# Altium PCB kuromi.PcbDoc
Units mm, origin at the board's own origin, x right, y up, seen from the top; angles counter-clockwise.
Board outline 67.61 x 64.44 mm, 2 copper layers (Top Layer, Bottom Layer); 19 components, 18 nets, 62 pads, 0 vias.
Unrouted connection lines stored in the file: 5.
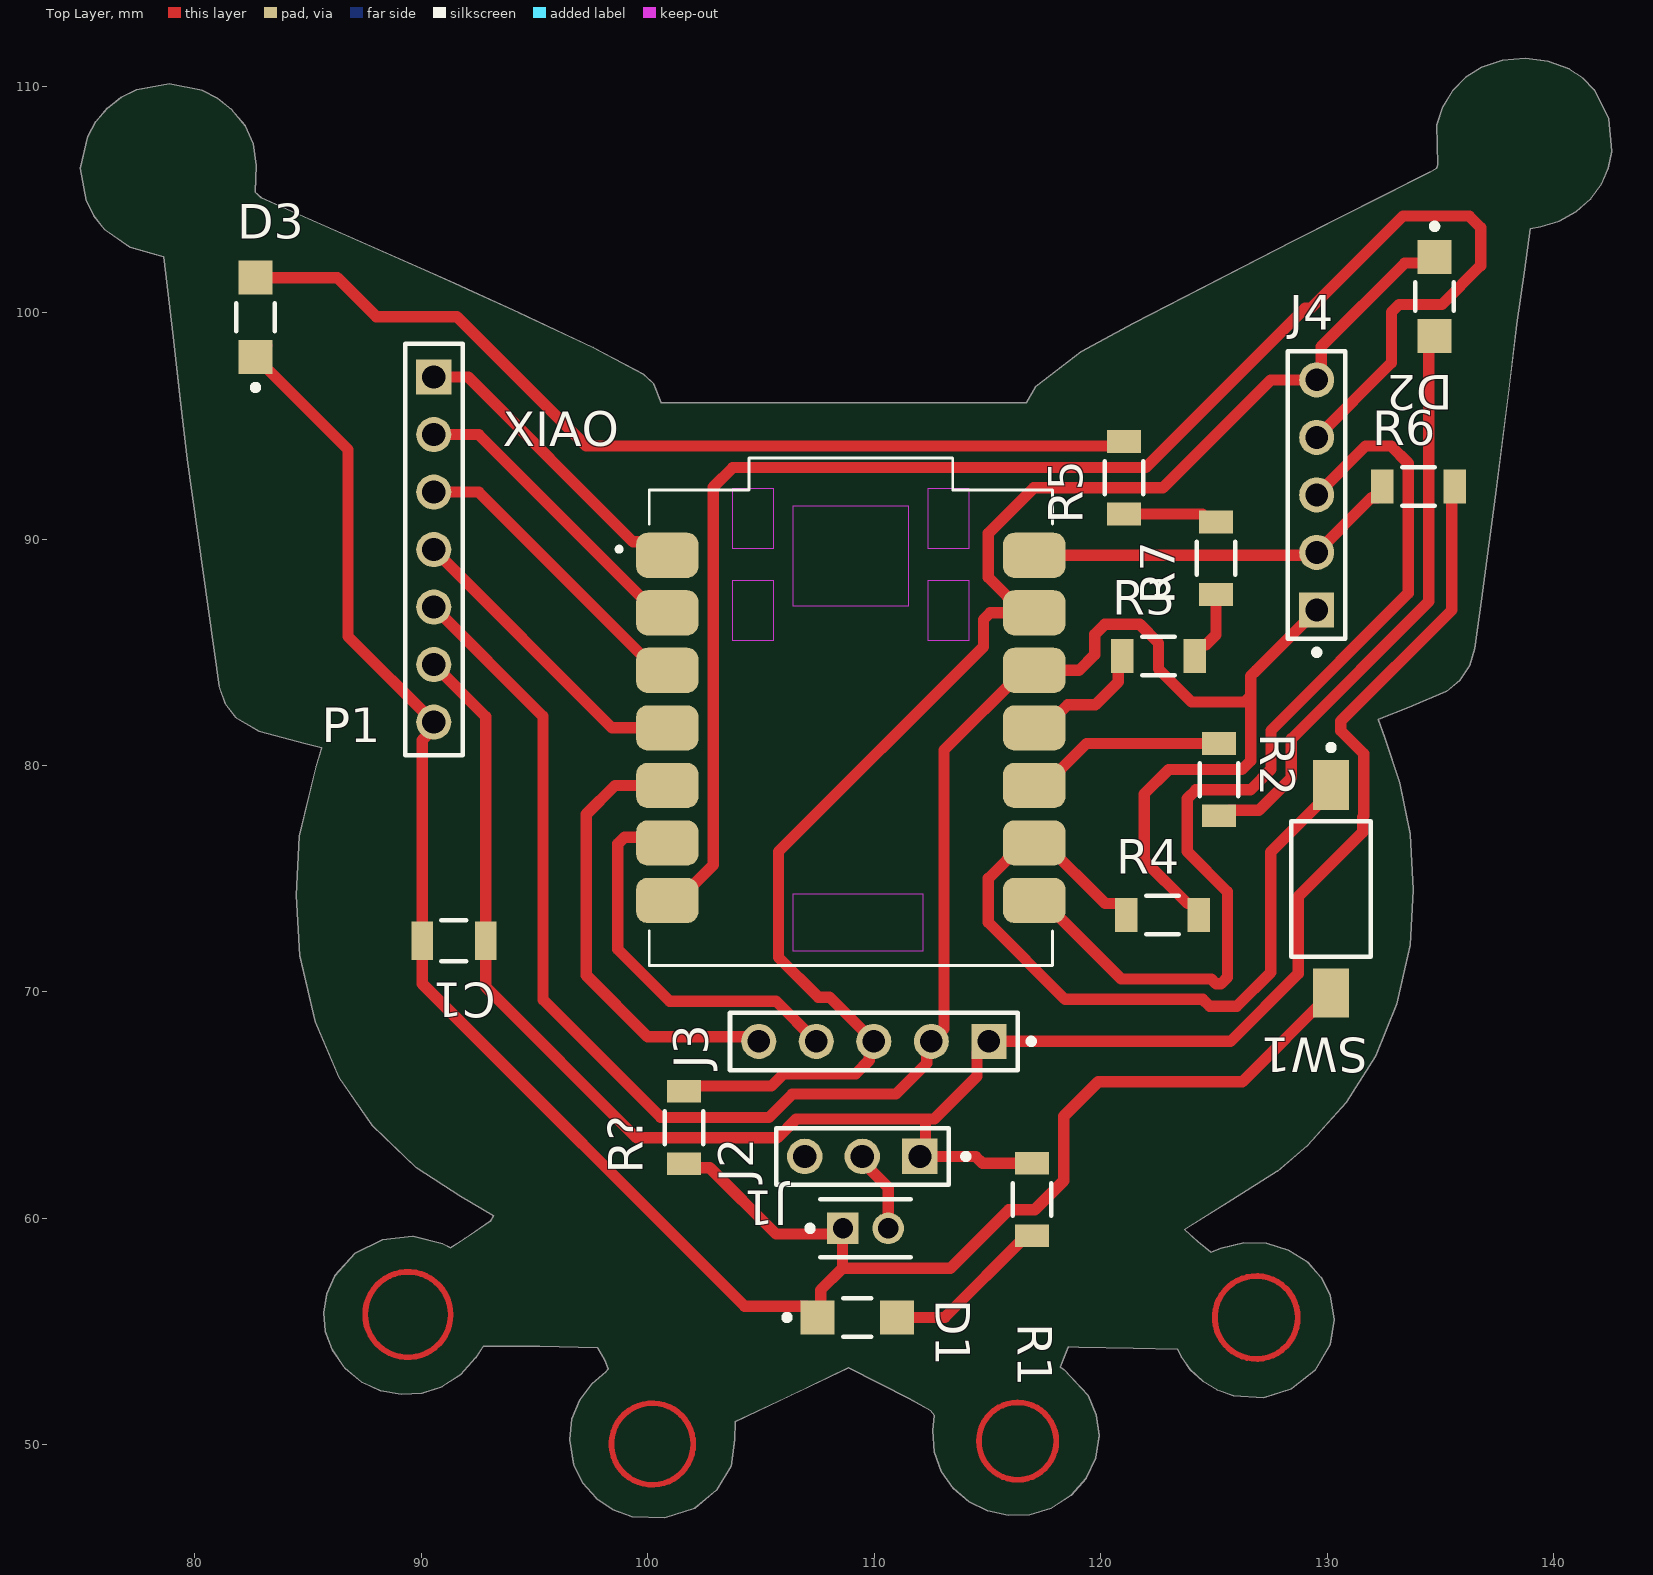
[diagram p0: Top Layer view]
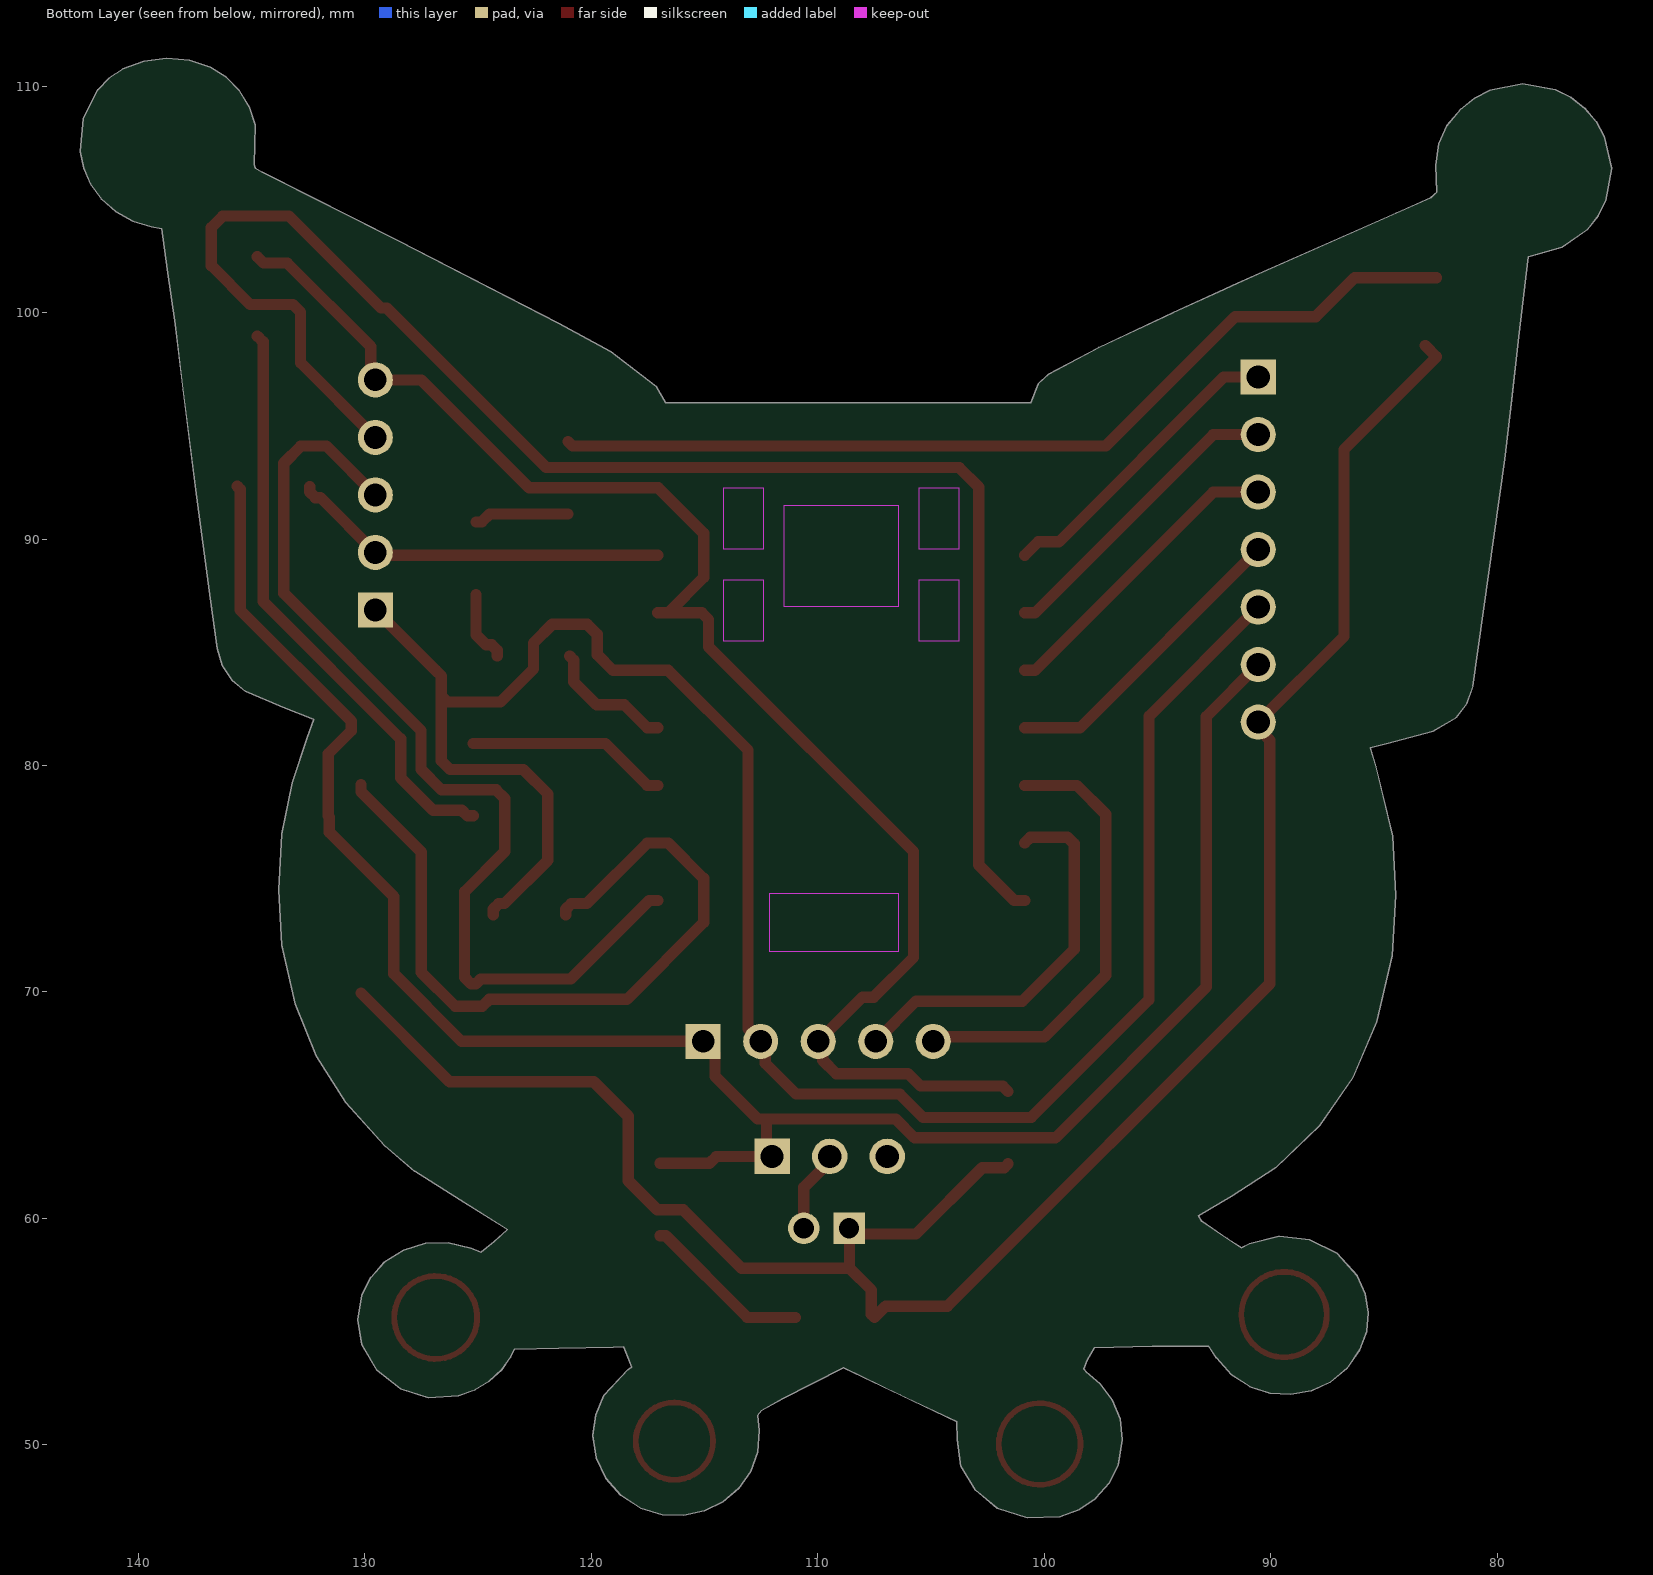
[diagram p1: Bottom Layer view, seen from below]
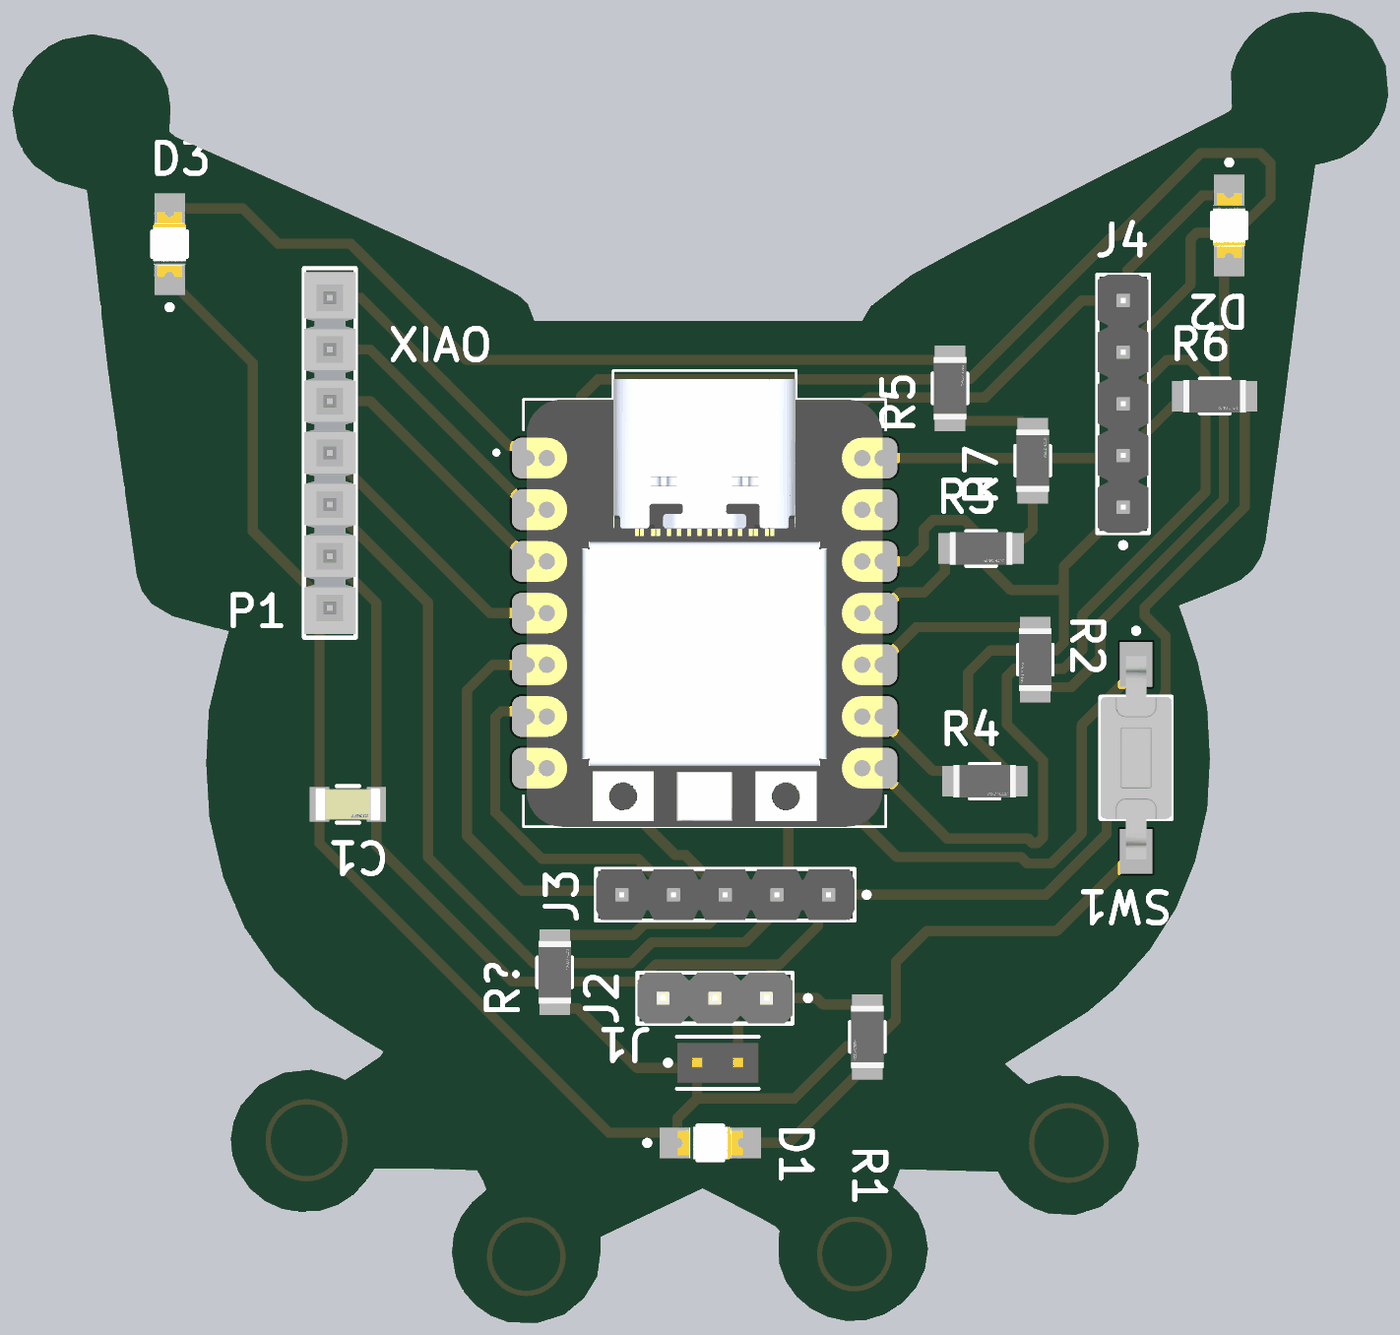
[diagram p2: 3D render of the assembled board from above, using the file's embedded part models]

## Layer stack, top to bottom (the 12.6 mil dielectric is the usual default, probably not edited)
Top Solder: solder mask 0.0102, Solder Resist, Dk 3.5
Top Layer: signal copper 0.0356
Dielectric 1: dielectric 0.32, FR-4, Dk 4.8
Bottom Layer: signal copper 0.0356
Bottom Solder: solder mask 0.0102, Solder Resist, Dk 3.5

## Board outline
86.633,53.379 87.363,52.775 88.206,52.389 89.114,52.226 90.036,52.287 90.923,52.575 91.727,53.093 92.397,53.844 92.749,54.364 95.221,54.364 97.798,54.283 98.098,53.75 98.248,53.349 98.159,53.228 97.542,52.701 96.998,51.982 96.65,51.147 96.557,50.23 96.731,49.113 97.133,48.318 97.723,47.649 98.462,47.14 99.315,46.823 99.316,46.818 100.748,46.779 102.073,47.198 103.043,48.004 103.684,49.063 103.849,50.236 103.862,51.017 106.358,52.204 108.872,53.4 111.55,52.033 112.486,51.515 112.66,51.299 112.583,50.641 112.647,49.682 112.965,48.819 113.493,48.08 114.189,47.492 115.012,47.084 115.92,46.883 116.869,46.916 117.819,47.21 118.697,47.773 119.365,48.529 119.791,49.426 119.942,50.416 119.797,51.317 119.451,52.177 118.382,53.322 118.223,53.428 118.391,53.878 118.56,54.329 119.029,54.321 121.448,54.262 123.397,54.214 123.568,53.88 123.959,53.318 124.505,52.82 125.156,52.422 125.862,52.161 127.193,52.087 128.437,52.487 129.463,53.291 130.14,54.43 130.306,55.524 130.145,56.612 129.734,57.394 129.15,58.067 128.298,58.589 127.318,58.909 126.328,58.924 125.313,58.674 124.867,58.502 124.286,58.979 123.704,59.51 125.79,60.824 127.797,62.075 129.139,63.218 130.845,65.12 132.141,67.174 133.067,69.463 133.667,72.071 133.797,74.51 133.665,76.974 133.202,79.239 132.545,81.24 132.263,82.036 133.621,82.564 135.275,83.27 135.864,83.761 136.299,84.414 136.521,85.168 136.834,87.385 137.479,92.18 138.032,96.623 138.379,99.486 138.718,101.915 138.971,103.696 139.434,103.787 140.249,104.034 140.998,104.454 141.635,105.013 142.116,105.681 142.413,106.385 142.56,107.117 142.434,108.567 141.792,109.843 141.293,110.358 140.685,110.76 139.753,111.097 138.743,111.223 137.738,111.137 136.823,110.837 136.115,110.388 135.538,109.797 135.109,109.089 134.849,108.288 134.885,106.529 134.843,106.383 134.53,106.19 128.526,103.173 121.448,99.529 119.138,98.276 117.134,96.735 116.71,96.012 100.601,96.012 100.274,96.851 99.804,97.283 97.588,98.462 94.323,100.003 92.291,100.927 91.463,101.296 90.529,101.715 84.451,104.4 82.932,105.077 82.656,105.327 82.719,106.509 82.582,107.459 82.223,108.253 81.62,108.972 81.001,109.465 80.323,109.819 78.871,110.112 77.422,109.849 76.749,109.508 76.136,109.028 75.63,108.438 75.263,107.785 74.949,106.369 75.198,104.942 75.534,104.277 76.013,103.671 77.131,102.889 78.305,102.549 78.618,102.465 79.052,98.927 79.354,96.162 79.662,93.529 81.067,83.504 81.335,82.731 81.802,82.121 82.825,81.518 84.896,80.952 85.601,80.786 85.35,79.949 84.608,76.876 84.479,74.274 84.638,71.609 85.319,68.683 86.366,66.215 87.837,64.099 89.791,62.23 91.74,60.981 93.195,60.121 93.039,59.868 91.923,59.113 91.291,58.706 90.95,58.872 89.629,59.218 88.282,59.066 87.076,58.465 86.177,57.465 85.824,56.66 85.688,55.838 85.768,55.012 86.065,54.199

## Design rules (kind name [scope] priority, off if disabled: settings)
Clearance [All] p1: gap=0.4 ignorepadtopadclearanceinfootprint=FALSE
PolygonConnect [All] p1: connectstyle=Relief reliefconductorwidth=0.254 reliefentries=4 polygonreliefangle="90 Angle" airgapwidth=0.254
RoutingVias [All] p1: holewidth=0.711 width=1.27 viastyle="Through Hole" minholewidth=0.711 minwidth=1.27 maxholewidth=0.711 maxwidth=1.27
SolderMaskExpansion [All] p1: expansion=0.102 istentingtop=FALSE
SupplyNets "Schematic Supply Nets_1" [InNet('GND')] p1: voltage=0.000
SupplyNets "Schematic Supply Nets" [InNet('VCC')] p2: voltage=0.000
Width [All] p1: maxlimit=0.5 minlimit=0.5 preferedwidth=0.5 minimp=50.000000 maximp=50.000000 favimp=50.000000
30 further rules are at their usual default settings.

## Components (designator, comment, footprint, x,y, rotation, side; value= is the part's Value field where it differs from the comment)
C1 "." FP-C1206C-EB-MFG 91.44,72.263 r180 top value="100 pF"
D1 "LED" FP-LTST-C150KSKT-MFG 109.248,55.626 r0 top
D2 "LED_1" FP-LTST-C150KSKT-MFG 134.747,100.711 r270 top
D3 "LED_2" FP-LTST-C150KSKT-MFG 82.677,99.794 r90 top
J1 "POWER" FP-TMM-102-01-L-S-MFG 109.617,59.563 r0 top
J2 "SWITCH" FP-PR20203VBNN-MFG 109.474,62.738 r180 top
J3 "I2C" FP-90120-0125-MFG 109.982,67.818 r180 top
J4 "TX-RX" FP-90120-0125-MFG 129.54,91.948 r90 top
P1 "OUTPUTS" SMTC-TSW-107-05-X-S 90.551,97.155 r270 top
R1 "." FP-AC1206-MFG 116.967,60.833 r270 top value=2.21KΩ
R2 "." FP-AC1206-MFG 125.222,79.375 r270 top value=2.21KΩ
R3 "." FP-AC1206-MFG 122.555,84.836 r0 top value=2.21KΩ
R4 "." FP-AC1206-MFG 122.733,73.406 r0 top value=2.21KΩ
R5 "." FP-AC1206-MFG 121.031,92.71 r90 top value=2.21KΩ
R6 "." FP-AC1206-MFG 134.036,92.329 r0 top value=2.21KΩ
R7 "." FP-AC1206-MFG 125.095,89.154 r90 top value=2.21KΩ
R? "." FP-AC1206-MFG 101.6,64.008 r90 top value=2.21KΩ
SW1 "BUTTON" TECO-FSMSM-2_V 130.175,74.549 r270 top
XIAO "102010428" MODULE_102010428 108.966,81.661 r0 top

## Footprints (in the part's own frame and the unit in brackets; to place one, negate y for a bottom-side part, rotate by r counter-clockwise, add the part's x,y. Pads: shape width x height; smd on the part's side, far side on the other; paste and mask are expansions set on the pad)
FP-90120-0125-MFG [mm]
  rect 1.55x1.55 hole 1 paste-2539.97 mask+0: 1(-5.08,0)
  round 1.55 hole 1 paste-2539.97 mask+0: 2(-2.54,0) 3(0,0) 4(2.54,0) 5(5.08,0)
  silkscreen extent -7.07,-1.27 6.35,1.27, body extent -6.45,-1.37 6.45,1.37, height 0.25
FP-AC1206-MFG [mm]
  rect 1x1.5 smd paste+0 mask+0: 1(-1.6,0) 2(1.6,0)
  silkscreen extent -0.72,-0.85 0.72,0.85, body extent -2.2,-0.95 2.2,0.95, height 0.25
FP-C1206C-EB-MFG [mm]
  rect 0.95x1.7 smd paste+0 mask+0: 1(-1.4,0) 2(1.4,0)
  silkscreen extent -0.55,-0.9 0.55,0.9, body extent -2,-1 2,1, height 0.25
FP-LTST-C150KSKT-MFG [mm]
  rect 1.5x1.5 smd paste+0 mask+0: 1(-1.75,0) 2(1.75,0)
  silkscreen extent -3.22,-0.85 0.63,0.85, body extent -2.6,-0.95 2.6,0.95, height 0.25
FP-PR20203VBNN-MFG [mm]
  rect 1.57x1.57 hole 1.02 paste-2539.97 mask+0: 1(-2.54,0)
  round 1.57 hole 1.02 paste-2539.97 mask+0: 2(0,0) 3(2.54,0)
  silkscreen extent -4.7,-1.25 3.81,1.25, body extent -3.91,-1.35 3.91,1.35, height 0.25
FP-TMM-102-01-L-S-MFG [mm]
  rect 1.39x1.39 hole 0.89 paste-2539.97 mask+0: 1(-1,0)
  round 1.39 hole 0.89 paste-2539.97 mask+0: 2(1,0)
  silkscreen extent -2.57,-1.28 2,1.28, body extent -2.1,-1.15 2.1,1.15, height 0.25
MODULE_102010428 [mm]
  rrect50% 2.75x2 smd: 1(-8.1,7.62) 2(-8.1,5.08) 3(-8.1,2.54) 4(-8.1,0) 5(-8.1,-2.54) 6(-8.1,-5.08) 7(-8.1,-7.62) 8(8.1,-7.62) 9(8.1,-5.08) 10(8.1,-2.54) 11(8.1,0) 12(8.1,2.54) 13(8.1,5.08) 14(8.1,7.62)
  Keep-Out Layer region: 2.54,5.375 -2.54,5.375 -2.54,9.82 2.54,9.82
  Keep-Out Layer region: 5.207,7.915 3.429,7.915 3.429,10.582 5.207,10.582
  Keep-Out Layer region: 5.207,3.851 3.429,3.851 3.429,6.518 5.207,6.518
  Keep-Out Layer region: -3.429,3.851 -5.207,3.851 -5.207,6.518 -3.429,6.518
  Keep-Out Layer region: -3.429,7.915 -5.207,7.915 -5.207,10.582 -3.429,10.582
  Keep-Out Layer region: 3.175,-9.865 -2.54,-9.865 -2.54,-7.325 3.175,-7.325
  silkscreen extent -10.33,-10.5 8.9,11.92, body extent -8.75,-10.5 8.75,11.5, height 4.41
SMTC-TSW-107-05-X-S [mm] ".025 SQ Post Terminal Strip Assembly, 1x7 Pins, Vertical, 2.54mm Pitch, Male"
  rect 1.55x1.55 hole 1.02: 1(0,0)
  round 1.55 hole 1.02: 2(2.54,0) 3(5.08,0) 4(7.62,0) 5(10.16,0) 6(12.7,0) 7(15.24,0)
  silkscreen extent -1.46,-1.27 16.7,1.27, body extent -1.27,-1.27 16.51,1.27, height 5.21
TECO-FSMSM-2_V [mm] "SMD, 2-Leads, Body 6x3.5mm, Pitch 9.19mm"
  rect 2.2x1.6 smd: 1(-4.595,0)
  rect 2.18x1.6 smd: 2(4.595,0)
  silkscreen extent -6.37,-1.75 3,1.75, body extent -4.98,-1.75 4.98,1.75, height 4.4

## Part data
C1: library part CMP-03020-023751-1, "C1206 100 pF X8R 10.00% 50 V", Capacitance="100 pF", Manufacturer=KEMET, Manufacturer Part Number=C1206C101K5HACTU, Package=C1206C-EB, Temperature="-55°C to +150°C", Temperature Characteristic=X8R, Temperature Coefficient=15%, Temperature Range High=+150°C, Temperature Range Low=-55°C, Tolerance=0.1, Voltage Rating="50 V"
D1 D2 D3: library part CMP-2000-06618-2, "LED YELLOW CLEAR 1206 SMD", Case Code (Imperial)=1206, Case Code (Metric)=3216, Color=Yellow, Forward Current=30mA, Forward Voltage=2.4V, Lens Color=Colorless, Max Operating Temperature=85°C, Min Operating Temperature=-55°C, Package Quantity=1, Power Dissipation=75mW, Reverse Voltage=5V, Test Current=20mA
J1: library part CMP-02766-001606-1, "CONN HEADER VERT 2POS 2MM", Housing Color=Black, Max Current Rating=3.9A, Max Operating Temperature=125°C, Max Voltage Rating (AC)=500V, Min Operating Temperature=-55°C
J2: library part CMP-77940-000002-1, "CONN HEADER VERT 3POS 2.54MM", Current Rating=3A, Manufacturer="Metz Connect", Manufacturer Part Number=PR20203VBNN, Temperature="-40°C to +105°C", Temperature Range High=+105°C, Temperature Range Low=-40°C
J3 J4: library part CMP-00257-00655425-1, "90120-0125 2.54mm Pitch C-Grid III Header, Single Row, Vertical, 5 Circuits, Tin (Sn) Plating", Contact Resistance=20mΩ, Current Rating=3A, Housing Color=Black, Manufacturer Lifecycle Status=ACTIVE, Max Operating Temperature=125°C, Max Voltage Rating (DC)=350.35kV, Min Operating Temperature=-55°C, Voltage Rating=350V
P1: library part CMP-1024-00402-1, "0.025\" SQ Post Header, Through-hole, Vertical, -55 to 125 degC, 2.54 mm Pitch, 7-Pin, Male, RoHS", Manufacturer=Samtec, PartNumber=TSW-107-05-F-S, Temperature Range="-55 to 125 degC"
R1 R2 R3 R4 R5 R6 R7 R?: library part CMP-03412-032679-1, "RES SMD 2.21K OHM 1% 1/4W 1206", Manufacturer=Yageo, Manufacturer Part Number=AC1206FR-072K21L, Package=AC1206, Power Rating=0.25W, Resistance=2.21KΩ, Temperature="-55°C to +155°C", Temperature Range High=+155°C, Temperature Range Low=-55°C, Tolerance=0.01, Voltage Rating=200V
SW1: library part CMP-2000-07511-1, "FSMSM Push Button Switch, 50 mA, -35 to 85 degC, 2-Pin SMD, RoHS, Bulk", Case\/Package=SMD/SMT, Contact Current Rating=50mA, Contact Resistance=100mOhm, Manufacturer="TE Connectivity", Max Operating Temperature=85degC, Max Voltage Rating (DC)=12V, Min Operating Temperature=-35degC, Operating Force=180gf, Package Description="2-Pin Surface Mount Device, Body 6 x 3.5 mm, Pitch 9.19 mm", Package Quantity=1000, Package Reference=FSMSM, Voltage Rating (DC)=24V
XIAO: "RP2040 XIAO RP2040 series ARMÂ® CortexÂ®-M0+ MCU 32-Bit Embedded Evaluation Board", Package=None

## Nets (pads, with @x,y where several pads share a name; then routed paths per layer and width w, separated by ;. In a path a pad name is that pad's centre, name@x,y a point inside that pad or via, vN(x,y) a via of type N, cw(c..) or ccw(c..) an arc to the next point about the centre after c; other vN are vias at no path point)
3V3: J3.2 J4.1 P1.5 R4.2 XIAO.12 | length 91.8
  Top Layer w0.5: P1.5 95.377,82.169 95.377,69.662 100.581,64.458 105.352,64.458 106.387,65.493 110.959,65.493 112.325,66.859 112.325,67.621 113.084,68.38 113.084,80.68 116.605,84.201 XIAO.12 119.047,84.201 119.741,84.895 119.741,85.792 120.186,86.236 121.724,86.236 122.555,85.405 122.555,84.267 124.018,82.804 126.365,82.804 126.622,83.061 ; R4.2 124.333,73.656 124.083,73.906 123.833,73.906 121.92,75.819 121.92,78.74 123.005,79.825 126.241,79.825 126.622,80.206 126.622,83.061 ; J4.1 126.873,84.201 126.622,83.95 126.622,83.061
5V: C1.1 J2.1 J3.1 J4.2 P1.6 R1.1 R6.1 R6.2 XIAO.14 | length 106.1
  Top Layer w0.5: P1.6 92.84,82.166 C1.1 92.84,70.228 99.51,63.558 105.725,63.558 106.556,64.389 112.268,64.389 112.649,64.389 ; 112.268,64.339 112.268,62.992 J2.1 114.481,62.738 114.786,62.433 R1.1 ; 112.684,64.424 114.537,66.277 114.537,67.293 J3.1 125.733,67.818 128.725,70.81 128.725,74.212 131.572,77.059 131.572,77.722 131.625,77.775 131.625,80.513 130.597,81.542 130.597,81.956 135.509,86.868 135.509,92.202 R6.2 ; XIAO.14 129.413,89.281 J4.2 131.961,91.829 132.186,91.829 132.436,92.079 R6.1@132.436,92.304
A0: P1.1 XIAO.1 | length 13.6
  Top Layer w0.5: P1.1 92.075,97.155 99.353,89.877 100.27,89.877 XIAO.1
A1: P1.2 XIAO.2 | length 13.6
  Top Layer w0.5: P1.2 92.531,94.615 100.405,86.741 XIAO.2
A2: P1.3 XIAO.3 | length 13.6
  Top Layer w0.5: P1.3 92.531,92.075 100.405,84.201 XIAO.3
A3: P1.4 XIAO.4 | length 13.6
  Top Layer w0.5: P1.4 98.425,81.661 XIAO.4
D8: R4.1 SW1.1 XIAO.9 | length 34.2
  Top Layer w0.5: R4.1 121.133,73.656 120.883,73.906 120.202,73.906 117.527,76.581 XIAO.9 116.605,76.581 115.041,75.017 115.041,73.065 118.431,69.675 124.511,69.675 124.822,69.364 126.006,69.364 127.508,70.866 127.508,76.177 130.175,78.844 SW1.1
D9: R2.1 XIAO.10 | length 8.9
  Top Layer w0.5: XIAO.10 117.527,79.121 119.381,80.975 R2.1
D10: D3.2 R3.1 R3.2 R5.1 R5.2 R7.1 R7.2 XIAO.11 | length 54.8
  Top Layer w0.5: D3.2 86.289,101.544 88.011,99.822 91.567,99.822 97.282,94.107 120.828,94.107 R5.2 ; XIAO.11 117.527,81.661 118.543,82.677 119.761,82.677 120.782,83.698 120.782,84.663 R3.1 ; R5.1 124.489,91.11 124.845,90.754 R7.2 ; R3.2 124.155,85.086 124.405,85.336 124.655,85.336 125.095,85.776 R7.1
GND: C1.2 D1.1 D2.1 D3.1 J1.1 J3.3 J4.5 P1.7 R?.1 R?.2 SW1.2 XIAO.13 | length 162.1
  Top Layer w0.5: D3.1@83.177,98.544 D3.1 86.764,93.957 86.764,85.702 P1.7 90.551,81.631 90.04,81.12 C1.2 90.04,70.361 104.275,56.126 106.998,56.126 D1.1 107.633,55.761 107.633,56.833 108.601,57.801 ; R?.1 101.773,62.235 102.738,62.235 105.664,59.309 108.363,59.309 J1.1 ; R?.2 101.836,65.844 105.465,65.844 106.014,66.393 109.192,66.393 109.781,66.982 109.781,67.617 J3.3 109.84,67.96 108.027,69.773 107.53,69.773 105.776,71.527 105.776,76.196 114.823,85.243 114.823,86.448 115.116,86.741 XIAO.13@116.605,86.741 ; J1.1@108.601,59.309 108.601,57.801 ; XIAO.13 XIAO.13@116.605,86.741 ; J4.5 127.508,97.028 122.74,92.26 117.044,92.26 115.041,90.257 115.041,88.305 XIAO.13@116.605,86.741 ; J4.5@129.741,97.229 129.741,98.499 133.434,102.192 134.478,102.192 D2.1 ; SW1.2 126.26,66.039 119.893,66.039 118.367,64.513 118.367,61.664 117.086,60.383 115.948,60.383 113.366,57.801 108.601,57.801
NetD1_2: D1.2 R1.2 | length 7.5
  Top Layer w0.5: D1.2 113.11,55.626 116.717,59.233 R1.2
NetD2_2: D2.2 R2.2 | length 26
  Top Layer w0.5: R2.2 125.472,77.775 125.722,78.025 126.987,78.025 128.422,79.46 128.422,81.175 134.486,87.239 134.486,87.369 134.486,93.348 134.493,93.355 134.493,98.707 D2.2
NetD3_2: 
RX: J4.3 XIAO.8 | length 44.3
  Top Layer w0.5: XIAO.8 117.441,74.041 120.907,70.575 124.884,70.575 125.101,70.358 125.31,70.358 125.603,70.651 125.603,74.422 123.822,76.203 123.822,78.544 124.203,78.925 126.614,78.925 127.522,79.833 127.522,81.548 133.586,87.612 133.586,90.937 133.586,93.348 132.827,94.107 131.699,94.107 J4.3
SCL: J3.4 XIAO.6 | length 17.5
  Top Layer w0.5: XIAO.6 100.612,76.835 98.972,76.835 98.679,76.542 98.679,71.882 100.965,69.596 105.664,69.596 J3.4
SDA: J3.5 XIAO.5 | length 20.1
  Top Layer w0.5: XIAO.5 98.552,79.121 97.282,77.851 97.282,70.739 100.002,68.019 104.701,68.019 J3.5
TX: J4.4 XIAO.7 | length 71.8
  Top Layer w0.5: XIAO.7 101.327,74.041 102.891,75.605 102.891,92.294 103.757,93.16 121.989,93.16 129.032,100.203 129.286,100.203 133.35,104.267 136.271,104.267 136.779,103.759 136.779,102.074 135.066,100.361 133.174,100.361 132.842,100.029 132.842,97.79 J4.4
VCC: J1.2 J2.2 | length 3.6
  Top Layer w0.5: J2.2 109.474,62.513 110.617,61.37 J1.2
pads on no net: J2.3
copper on no net: | length 45.4
  Top Layer w0.254: 91.296,55.753 ccw(c89.408,55.753) 91.296,55.753 ; 102.008,50.038 ccw(c100.203,50.038) 102.008,50.038 ; 118.041,50.165 ccw(c116.332,50.165) 118.041,50.165 ; 128.705,55.626 ccw(c126.873,55.626) 128.705,55.626

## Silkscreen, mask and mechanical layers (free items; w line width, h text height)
Mechanical 2:
  drawing of 188 lines, arcs and shapes, not listed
